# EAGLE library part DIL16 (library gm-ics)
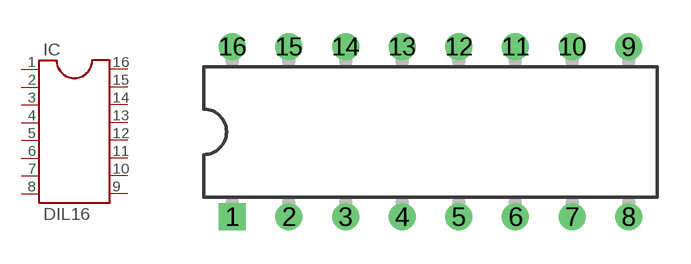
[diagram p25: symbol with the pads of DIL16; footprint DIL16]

Designator prefix IC

## DIL16  [DIL16]
1  1  pas
2  2  pas
3  3  pas
4  4  pas
5  5  pas
6  6  pas
7  7  pas
8  8  pas
9  9  pas
10  10  pas
11  11  pas
12  12  pas
13  13  pas
14  14  pas
15  15  pas
16  16  pas

## Footprint DIL16 (pad centres in mm)
Dual In Line Package
drill 0.7 square: 1 -8.89,-3.81
drill 0.7 round: 2 -6.35,-3.81; 3 -3.81,-3.81; 4 -1.27,-3.81; 5 1.27,-3.81; 6 3.81,-3.81; 7 6.35,-3.81; 8 8.89,-3.81; 9 8.89,3.81; 10 6.35,3.81; 11 3.81,3.81; 12 1.27,3.81; 13 -1.27,3.81; 14 -3.81,3.81; 15 -6.35,3.81; 16 -8.89,3.81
